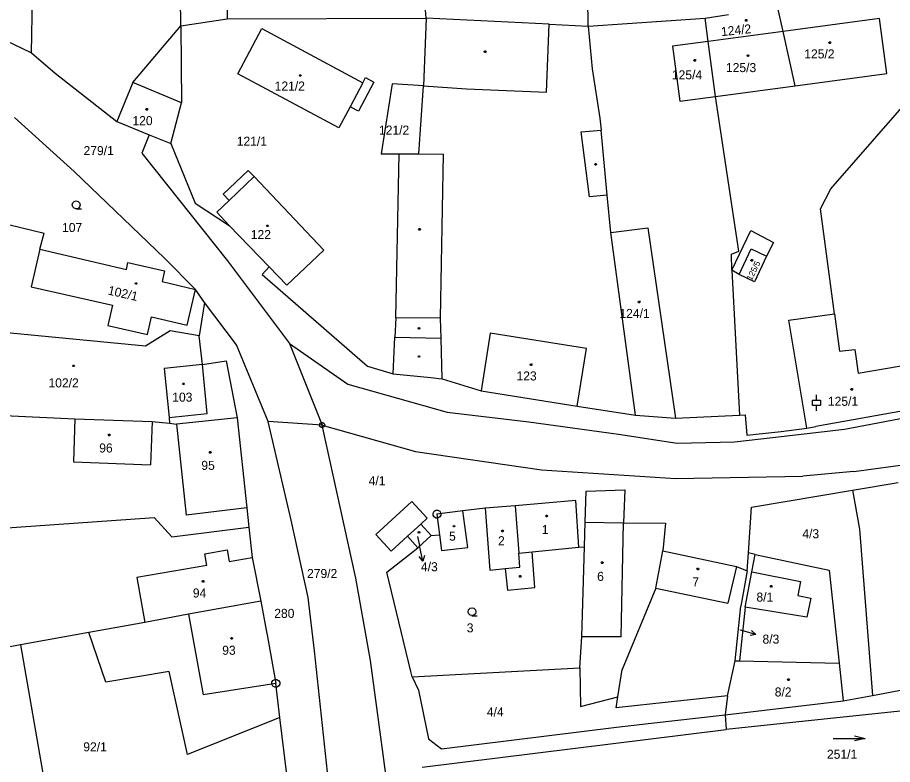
# Model space of a CAD drawing. Extents: x -812394 to -807601, y -1013098 to -1009266.
# Drawn here: x -809776.7 to -809612.2, y -1010813 to -1010672.7 of the extents above; entities that cross this region are included whole.
import ezdxf

# ---------------------------------------------------------------- set-up
doc = ezdxf.new("R2010")
doc.units = 0
for name, color, linetype in [('KN_HRANICE', 7, 'Continuous'), ('KN_KULTURY', 7, 'Continuous'), ('KN_MEZNIKY', 7, 'Continuous'), ('KN_PARCELY', 7, 'Continuous'), ('KN_SLUCKY', 7, 'Continuous')]:
    doc.layers.add(name, color=color, linetype=linetype)

# ---------------------------------------------------------------- blocks, each defined once
blk = doc.blocks.new('101')
blk.add_line((-0.05, 0), (0.05, 0))
blk.add_lwpolyline([(0.19, 0.72), (0.53, 0.53), (0.72, 0.19), (0.72, -0.2), (0.53, -0.54), (0.19, -0.73), (-0.2, -0.73), (-0.54, -0.54), (-0.73, -0.2), (-0.73, 0.19), (-0.54, 0.53), (-0.2, 0.72), (0.19, 0.72)])
blk = doc.blocks.new('304')
blk.add_lwpolyline([(0, 0), (-0.38, 0.1), (-0.65, 0.37), (-0.75, 0.74), (-0.65, 1.11), (-0.38, 1.38), (-0.01, 1.48), (0.36, 1.38), (0.63, 1.11), (0.73, 0.73), (0.63, 0.35), (0.36, 0.08), (-0.02, -0.02), (0.98, -0.02)])
blk = doc.blocks.new('NAHRADNI_SYMBOL')
blk.add_lwpolyline([(0.09, 0.15), (0.18, 0), (0.09, -0.15), (-0.09, -0.15), (-0.18, 0), (-0.09, 0.15), (0.09, 0.15)])
blk = doc.blocks.new('802')
blk.add_line((-3, 0), (3, 0))
blk.add_lwpolyline([(1, 0.5), (3, 0), (1, -0.5)])
blk = doc.blocks.new('10292')
blk.add_line((0, 3), (0, 0))
blk.add_lwpolyline([(-0.5, 2), (0, 3), (0.5, 2)])
blk = doc.blocks.new('318')
blk.add_line((0, 2), (0, 3))
blk.add_lwpolyline([(0, 0), (0, 1), (-0.75, 1), (-0.75, 2), (0, 2), (0.75, 2), (0.75, 1), (0, 1)])
blk = doc.blocks.new('402')
blk.add_lwpolyline([(0.09, 0.15), (0.18, 0), (0.09, -0.15), (-0.09, -0.15), (-0.18, 0), (-0.09, 0.15), (0.09, 0.15)])
blk = doc.blocks.new('105')
blk.add_line((-0.12, 0), (0.12, 0))
blk.add_lwpolyline([(0.15, 0.48), (0.4, 0.3), (0.5, 0.01), (0.4, -0.28), (0.15, -0.46), (-0.16, -0.46), (-0.41, -0.28), (-0.51, 0.01), (-0.41, 0.3), (-0.16, 0.48), (0.15, 0.48)])

msp = doc.modelspace()

# ---------------------------------------------------------------- linework, layer by layer
at = {"layer": 'KN_HRANICE'}
for p, q in [((-809669.42, -1010674.32), (-809670.02, -1010597.72)), ((-809738.29, -1010601.65), (-809737.29, -1010672.93)), ((-809745.99, -1010674.27), (-809746.74, -1010602.54)), ((-809699.85, -1010672.81), (-809703, -1010635.36)), ((-809774.04, -1010679.33), (-809773.49, -1010652.65)), ((-809632.78, -1010675.32), (-809633.83, -1010670.62)), ((-809737.29, -1010672.93), (-809699.85, -1010672.81)), ((-809699.85, -1010672.81), (-809700.37, -1010685.55)), ((-809676.74, -1010673.97), (-809699.85, -1010672.81)), ((-809669.42, -1010674.32), (-809647.44, -1010672.82)), ((-809647.44, -1010672.82), (-809643.04, -1010672.11)), ((-809646.86, -1010677.2), (-809647.44, -1010672.82)), ((-809614.65, -1010672.88), (-809632.78, -1010675.32)), ((-809613.27, -1010683.22), (-809614.65, -1010672.88)), ((-809784.4, -1010674.33), (-809774.04, -1010679.33)), ((-809754.98, -1010684.91), (-809745.99, -1010674.27)), ((-809745.99, -1010674.27), (-809737.29, -1010672.93)), ((-809745.99, -1010674.27), (-809745.83, -1010688.74)), ((-809676.74, -1010673.97), (-809669.42, -1010674.32)), ((-809669.42, -1010674.32), (-809668.69, -1010682.36)), ((-809735.29, -1010683.27), (-809730.75, -1010674.77)), ((-809730.75, -1010674.77), (-809711.79, -1010684.94)), ((-809632.78, -1010675.32), (-809646.86, -1010677.2)), ((-809630.51, -1010685.51), (-809632.78, -1010675.32)), ((-809646.86, -1010677.2), (-809653.59, -1010678.08)), ((-809645.48, -1010687.51), (-809646.86, -1010677.2)), ((-809774.04, -1010679.33), (-809769.56, -1010683.18)), ((-809653.59, -1010678.08), (-809652.21, -1010688.42)), ((-809668.69, -1010682.36), (-809667.2, -1010691.63)), ((-809769.56, -1010683.18), (-809758.03, -1010692.2)), ((-809716.29, -1010693.43), (-809735.29, -1010683.27)), ((-809711.79, -1010684.94), (-809711.27, -1010683.97)), ((-809711.27, -1010683.97), (-809709.68, -1010684.81)), ((-809630.51, -1010685.51), (-809613.27, -1010683.22)), ((-809754.98, -1010684.91), (-809758.03, -1010692.2)), ((-809709.68, -1010684.81), (-809712.59, -1010690.29)), ((-809706.24, -1010685.14), (-809708.32, -1010698.31)), ((-809700.37, -1010685.55), (-809706.24, -1010685.14)), ((-809701.22, -1010698.32), (-809700.37, -1010685.55)), ((-809645.48, -1010687.51), (-809630.51, -1010685.51)), ((-809652.21, -1010688.42), (-809645.48, -1010687.51)), ((-809641.11, -1010716.62), (-809645.48, -1010687.51)), ((-809747.86, -1010696.38), (-809745.83, -1010688.74)), ((-809714.18, -1010689.45), (-809716.29, -1010693.43)), ((-809712.59, -1010690.29), (-809714.18, -1010689.45)), ((-809777.22, -1010691.48), (-809766.01, -1010701.62)), ((-809758.03, -1010692.2), (-809751.95, -1010694.73)), ((-809667.2, -1010691.63), (-809666.99, -1010693.85)), ((-809665.84, -1010706.07), (-809666.99, -1010693.85)), ((-809751.95, -1010694.73), (-809753.31, -1010698.15)), ((-809751.95, -1010694.73), (-809747.86, -1010696.38)), ((-809747.86, -1010696.38), (-809743.3, -1010707.57)), ((-809753.31, -1010698.15), (-809737.22, -1010718.42)), ((-809708.32, -1010698.31), (-809704.94, -1010698.29)), ((-809705.58, -1010729.13), (-809704.94, -1010698.29)), ((-809704.94, -1010698.29), (-809701.22, -1010698.32)), ((-809766.01, -1010701.62), (-809749.02, -1010717.93)), ((-809738.02, -1010705.9), (-809733.32, -1010701.42)), ((-809733.32, -1010701.42), (-809732.21, -1010702.59)), ((-809732.21, -1010702.59), (-809719.07, -1010716.39)), ((-809739.24, -1010709.28), (-809736.91, -1010707.06)), ((-809736.91, -1010707.06), (-809738.02, -1010705.9)), ((-809665.18, -1010713.11), (-809665.84, -1010706.07)), ((-809743.3, -1010707.57), (-809736.88, -1010711.74)), ((-809736.88, -1010711.74), (-809739.24, -1010709.28)), ((-809781.21, -1010710.87), (-809771.66, -1010713.22)), ((-809729.37, -1010719.53), (-809736.88, -1010711.74)), ((-809772.47, -1010716.21), (-809771.66, -1010713.22)), ((-809660.52, -1010747.43), (-809665.18, -1010713.11)), ((-809642.41, -1010720.19), (-809638.87, -1010712.74)), ((-809638.87, -1010712.74), (-809634.6, -1010714.95)), ((-809634.6, -1010714.95), (-809635.89, -1010717.53)), ((-809772.47, -1010716.21), (-809756.21, -1010720.01)), ((-809719.07, -1010716.39), (-809726.06, -1010722.97)), ((-809642.51, -1010717.16), (-809641.11, -1010716.62)), ((-809642.41, -1010720.19), (-809642.51, -1010717.16)), ((-809756.21, -1010720.01), (-809755.91, -1010718.7)), ((-809755.91, -1010718.7), (-809749.04, -1010720.31)), ((-809749.02, -1010717.93), (-809743.23, -1010723.77)), ((-809737.22, -1010718.42), (-809725.56, -1010733.93)), ((-809635.89, -1010717.53), (-809638.17, -1010722.36)), ((-809749.04, -1010720.31), (-809749.51, -1010722.3)), ((-809729.37, -1010719.53), (-809730.7, -1010720.97)), ((-809726.06, -1010722.97), (-809729.37, -1010719.53)), ((-809642.41, -1010720.19), (-809641.01, -1010747.39)), ((-809641.03, -1010721), (-809642.41, -1010720.19)), ((-809730.7, -1010720.97), (-809710.9, -1010738.19)), ((-809638.17, -1010722.36), (-809641.03, -1010721)), ((-809749.51, -1010722.3), (-809743.23, -1010723.77)), ((-809741.5, -1010726.25), (-809743.23, -1010723.77)), ((-809741.5, -1010726.25), (-809742.53, -1010732.53)), ((-809735.54, -1010734.22), (-809741.5, -1010726.25)), ((-809623.13, -1010728.35), (-809622.2, -1010735.4)), ((-809705.58, -1010729.13), (-809705.74, -1010732.73)), ((-809752.63, -1010734.46), (-809779.32, -1010731.85)), ((-809747.95, -1010731.58), (-809752.63, -1010734.46)), ((-809742.53, -1010732.53), (-809747.95, -1010731.58)), ((-809741.93, -1010737.9), (-809742.53, -1010732.53)), ((-809706.04, -1010739.63), (-809705.74, -1010732.73)), ((-809729.55, -1010748.61), (-809735.54, -1010734.22)), ((-809725.56, -1010733.93), (-809719.43, -1010749.27)), ((-809725.56, -1010733.93), (-809714.56, -1010741.6)), ((-809741.93, -1010737.9), (-809749.09, -1010738.63)), ((-809749.09, -1010738.63), (-809748.19, -1010747.84)), ((-809741.93, -1010737.9), (-809737.44, -1010737.2)), ((-809737.44, -1010737.2), (-809735.38, -1010747.89)), ((-809710.9, -1010738.19), (-809706.04, -1010739.63)), ((-809618.66, -1010739.51), (-809608.17, -1010737.7)), ((-809706.04, -1010739.63), (-809698.97, -1010740.34)), ((-809714.56, -1010741.6), (-809695.94, -1010746.84)), ((-809698.97, -1010740.34), (-809697.48, -1010740.51)), ((-809697.48, -1010740.51), (-809696.89, -1010740.57)), ((-809696.89, -1010740.57), (-809689.54, -1010742.83)), ((-809689.54, -1010742.83), (-809671.5, -1010745.72)), ((-809695.94, -1010746.84), (-809680.59, -1010748.64)), ((-809671.5, -1010745.72), (-809660.52, -1010747.43)), ((-809606.66, -1010745.99), (-809626.64, -1010749.55)), ((-809621.25, -1010750.05), (-809601.6, -1010746.29)), ((-809785.91, -1010747.13), (-809765.89, -1010748.07)), ((-809765.89, -1010748.07), (-809766.17, -1010756.16)), ((-809765.89, -1010748.07), (-809751.37, -1010748.58)), ((-809748.19, -1010747.84), (-809748.08, -1010748.94)), ((-809735.38, -1010747.89), (-809746.82, -1010749.08)), ((-809735.38, -1010747.89), (-809733.57, -1010764.79)), ((-809660.52, -1010747.43), (-809652.99, -1010747.99)), ((-809652.99, -1010747.99), (-809641.01, -1010747.39)), ((-809641.01, -1010747.39), (-809639.91, -1010747.34)), ((-809639.91, -1010747.34), (-809639.63, -1010751.19)), ((-809751.37, -1010748.58), (-809751.66, -1010756.76)), ((-809751.37, -1010748.58), (-809748.08, -1010748.94)), ((-809748.08, -1010748.94), (-809746.82, -1010749.08)), ((-809719.43, -1010749.27), (-809729.55, -1010748.61)), ((-809725.23, -1010767.15), (-809729.55, -1010748.61)), ((-809713.08, -1010778.05), (-809719.43, -1010749.27)), ((-809719.43, -1010749.27), (-809701.9, -1010754.25)), ((-809680.59, -1010748.64), (-809663.74, -1010750.97)), ((-809634.81, -1010751.63), (-809621.25, -1010750.05)), ((-809633.16, -1010750.47), (-809628.36, -1010749.86)), ((-809628.36, -1010749.86), (-809626.64, -1010749.55)), ((-809663.74, -1010750.97), (-809652.69, -1010752.68)), ((-809641.93, -1010752.44), (-809634.81, -1010751.63)), ((-809639.63, -1010751.19), (-809633.16, -1010750.47)), ((-809652.69, -1010752.68), (-809641.93, -1010752.44)), ((-809701.9, -1010754.25), (-809678.17, -1010757.69)), ((-809766.17, -1010756.16), (-809751.66, -1010756.76)), ((-809619.48, -1010758), (-809604.22, -1010755.92)), ((-809678.17, -1010757.69), (-809652.96, -1010759.33)), ((-809619.48, -1010758), (-809629.11, -1010758.87)), ((-809652.96, -1010759.33), (-809629.11, -1010758.87)), ((-809669.98, -1010767.52), (-809669.8, -1010761.66)), ((-809669.8, -1010761.66), (-809662.52, -1010761.44)), ((-809662.52, -1010761.44), (-809662.78, -1010767.62)), ((-809638.74, -1010764.69), (-809619.76, -1010761.5)), ((-809619.76, -1010761.5), (-809611.19, -1010760.06)), ((-809619.76, -1010761.5), (-809618.42, -1010768.8)), ((-809733.57, -1010764.79), (-809733.18, -1010768.47)), ((-809702.57, -1010763.63), (-809709.33, -1010769.84)), ((-809699.69, -1010766.77), (-809702.57, -1010763.63)), ((-809688.81, -1010764.89), (-809692.96, -1010765.39)), ((-809683.14, -1010764.42), (-809688.81, -1010764.89)), ((-809688.81, -1010764.89), (-809687.88, -1010776.52)), ((-809671.72, -1010763.46), (-809683.14, -1010764.42)), ((-809683.14, -1010764.42), (-809682.45, -1010773.34)), ((-809671.19, -1010772.24), (-809671.72, -1010763.46)), ((-809639.3, -1010773.28), (-809638.74, -1010764.69)), ((-809692.96, -1010765.39), (-809697.85, -1010765.98)), ((-809697.85, -1010765.98), (-809697.36, -1010769.88)), ((-809692.01, -1010772.28), (-809692.96, -1010765.39)), ((-809794.5, -1010769.7), (-809750.96, -1010766.66)), ((-809750.96, -1010766.66), (-809747.68, -1010770.25)), ((-809722.03, -1010781.65), (-809725.23, -1010767.15)), ((-809700.87, -1010767.86), (-809699.69, -1010766.77)), ((-809698.9, -1010770), (-809700.87, -1010767.86)), ((-809670.12, -1010772.14), (-809669.98, -1010767.52)), ((-809662.78, -1010767.62), (-809654.89, -1010767.73)), ((-809654.89, -1010767.73), (-809655.37, -1010772.93)), ((-809747.68, -1010770.25), (-809733.18, -1010768.47)), ((-809733.18, -1010768.47), (-809732.57, -1010774.14)), ((-809709.33, -1010769.84), (-809706.45, -1010772.98)), ((-809698.9, -1010770), (-809697.36, -1010769.88)), ((-809697.36, -1010769.88), (-809696.98, -1010772.84)), ((-809618.42, -1010768.8), (-809615.96, -1010800.09)), ((-809706.45, -1010772.98), (-809703.38, -1010770.17)), ((-809703.38, -1010770.17), (-809701.41, -1010772.31)), ((-809701.41, -1010772.31), (-809698.9, -1010770)), ((-809707.23, -1010776.9), (-809701.41, -1010772.31)), ((-809696.98, -1010772.84), (-809692.01, -1010772.28)), ((-809682.45, -1010773.34), (-809679.95, -1010773.09)), ((-809679.95, -1010773.09), (-809671.19, -1010772.24)), ((-809679.45, -1010779.76), (-809679.95, -1010773.09)), ((-809671.19, -1010772.24), (-809670.12, -1010772.14)), ((-809670.64, -1010789.08), (-809670.12, -1010772.14)), ((-809656.71, -1010779.93), (-809655.37, -1010772.93)), ((-809655.37, -1010772.93), (-809641.57, -1010775.83)), ((-809732.57, -1010774.14), (-809730.91, -1010782.33)), ((-809639.52, -1010776.68), (-809639.3, -1010773.28)), ((-809638.02, -1010773.59), (-809639.3, -1010773.28)), ((-809638.65, -1010776.84), (-809638.02, -1010773.59)), ((-809638.02, -1010773.59), (-809624.14, -1010776.53)), ((-809687.88, -1010776.52), (-809685.04, -1010776.24)), ((-809685.04, -1010776.24), (-809684.59, -1010780.3)), ((-809641.57, -1010775.83), (-809639.52, -1010776.68)), ((-809710.32, -1010793.53), (-809713.08, -1010778.05)), ((-809702.75, -1010795.56), (-809707.23, -1010776.9)), ((-809639.52, -1010776.68), (-809640.74, -1010783.28)), ((-809639.93, -1010783.49), (-809638.65, -1010776.84)), ((-809624.14, -1010776.53), (-809622.24, -1010794)), ((-809684.59, -1010780.3), (-809679.45, -1010779.76)), ((-809656.71, -1010779.93), (-809663.05, -1010795.21)), ((-809730.91, -1010782.33), (-809744.52, -1010784.82)), ((-809730.91, -1010782.33), (-809729.89, -1010788.11)), ((-809720.85, -1010791.69), (-809722.03, -1010781.65)), ((-809641.81, -1010793.54), (-809640.74, -1010783.28)), ((-809639.93, -1010783.49), (-809640.99, -1010793.56)), ((-809752.77, -1010786.34), (-809763.26, -1010788.24)), ((-809744.52, -1010784.82), (-809752.77, -1010786.34)), ((-809763.26, -1010788.24), (-809776.12, -1010790.59)), ((-809760.07, -1010797.59), (-809763.26, -1010788.24)), ((-809729.89, -1010788.11), (-809729.78, -1010788.7)), ((-809729.78, -1010788.7), (-809728.11, -1010797.8)), ((-809671, -1010794.86), (-809670.64, -1010789.08)), ((-809776.12, -1010790.59), (-809802.82, -1010795.47)), ((-809776.12, -1010790.59), (-809768.91, -1010832.11)), ((-809718.25, -1010816.21), (-809720.85, -1010791.69)), ((-809707.49, -1010814.44), (-809710.32, -1010793.53)), ((-809643.26, -1010800.13), (-809641.81, -1010793.54)), ((-809641.81, -1010793.54), (-809640.99, -1010793.56)), ((-809640.99, -1010793.56), (-809622.24, -1010794)), ((-809622.24, -1010794), (-809621.47, -1010801.11)), ((-809748.14, -1010795.55), (-809760.07, -1010797.59)), ((-809744.75, -1010811.18), (-809748.14, -1010795.55)), ((-809702.5, -1010796.59), (-809702.75, -1010795.56)), ((-809702.5, -1010796.59), (-809671, -1010794.86)), ((-809671, -1010794.86), (-809670.86, -1010802.13)), ((-809663.83, -1010800.36), (-809663.05, -1010795.21)), ((-809615.96, -1010800.09), (-809588.54, -1010794.9)), ((-809727.35, -1010804.19), (-809728.11, -1010797.8)), ((-809702.5, -1010796.59), (-809701.33, -1010799.05)), ((-809701.33, -1010799.05), (-809699.46, -1010808.24)), ((-809670.86, -1010802.13), (-809663.83, -1010800.36)), ((-809664.14, -1010802.41), (-809663.83, -1010800.36)), ((-809643.26, -1010800.13), (-809657.25, -1010801.66)), ((-809643.26, -1010800.13), (-809643.65, -1010803.69)), ((-809643.65, -1010803.69), (-809621.47, -1010801.11)), ((-809621.47, -1010801.11), (-809615.96, -1010800.09)), ((-809657.25, -1010801.66), (-809664.14, -1010802.41)), ((-809600.38, -1010801.89), (-809643.49, -1010806.47)), ((-809727.35, -1010804.19), (-809744.75, -1010811.18)), ((-809726.02, -1010815.44), (-809727.35, -1010804.19)), ((-809657.57, -1010805.27), (-809643.65, -1010803.69)), ((-809643.65, -1010803.69), (-809643.49, -1010806.47)), ((-809696.99, -1010810.11), (-809664.09, -1010806.01)), ((-809664.09, -1010806.01), (-809657.57, -1010805.27)), ((-809700.6, -1010813.52), (-809643.49, -1010806.47)), ((-809699.46, -1010808.24), (-809696.99, -1010810.11))]:
    msp.add_line(p, q, dxfattribs=at)
for points in [[(-809623.13, -1010728.35), (-809625.78, -1010708.61), (-809623.83, -1010704.87), (-809603.55, -1010681.64)], [(-809622.2, -1010735.4), (-809619.34, -1010735.04), (-809618.66, -1010739.51)]]:
    msp.add_lwpolyline(points, dxfattribs=at)
at = {"layer": 'KN_PARCELY'}
for p, q in [((-809701.47, -1010770.18), (-809701.11, -1010771.9)), ((-809640.83, -1010787.76), (-809640.77, -1010787.78))]:
    msp.add_line(p, q, dxfattribs=at)
at = {"layer": 'KN_SLUCKY'}
for p, q in [((-809677.26, -1010686.71), (-809676.74, -1010673.97)), ((-809745.83, -1010688.74), (-809754.98, -1010684.91)), ((-809711.79, -1010684.94), (-809714.18, -1010689.45)), ((-809700.37, -1010685.55), (-809692.3, -1010686.07)), ((-809692.3, -1010686.07), (-809677.26, -1010686.71)), ((-809670.75, -1010694.2), (-809666.99, -1010693.85)), ((-809669.2, -1010706.39), (-809670.75, -1010694.2)), ((-809701.22, -1010698.32), (-809696.59, -1010698.39)), ((-809697.15, -1010729.18), (-809696.59, -1010698.39)), ((-809736.91, -1010707.06), (-809732.21, -1010702.59)), ((-809665.84, -1010706.07), (-809669.2, -1010706.39)), ((-809665.18, -1010713.11), (-809658.18, -1010712.2)), ((-809658.18, -1010712.2), (-809652.99, -1010747.99)), ((-809772.47, -1010716.21), (-809774.12, -1010723.27)), ((-809641.03, -1010721), (-809638.78, -1010716.15)), ((-809638.78, -1010716.15), (-809635.89, -1010717.53)), ((-809774.12, -1010723.27), (-809758.82, -1010726.77)), ((-809744.81, -1010730.49), (-809743.23, -1010723.77)), ((-809758.82, -1010726.77), (-809759.68, -1010730.55)), ((-809631.7, -1010729.58), (-809623.13, -1010728.35)), ((-809752.23, -1010732.25), (-809751.48, -1010728.96)), ((-809751.48, -1010728.96), (-809744.81, -1010730.49)), ((-809697.15, -1010729.18), (-809705.58, -1010729.13)), ((-809697.06, -1010732.94), (-809697.15, -1010729.18)), ((-809628.36, -1010749.86), (-809631.7, -1010729.58)), ((-809759.68, -1010730.55), (-809752.23, -1010732.25)), ((-809687.81, -1010731.99), (-809689.54, -1010742.83)), ((-809669.72, -1010734.88), (-809687.81, -1010731.99)), ((-809705.74, -1010732.73), (-809697.06, -1010732.94)), ((-809696.89, -1010740.57), (-809697.06, -1010732.94)), ((-809671.5, -1010745.72), (-809669.72, -1010734.88)), ((-809741.03, -1010747.11), (-809741.93, -1010737.9)), ((-809748.19, -1010747.84), (-809741.03, -1010747.11)), ((-809746.82, -1010749.08), (-809744.99, -1010766.19)), ((-809733.57, -1010764.79), (-809744.99, -1010766.19)), ((-809703.38, -1010770.17), (-809700.87, -1010767.86)), ((-809669.98, -1010767.52), (-809662.78, -1010767.62)), ((-809663.25, -1010789.07), (-809662.78, -1010767.62)), ((-809741.47, -1010773.44), (-809737.24, -1010772.71)), ((-809737.24, -1010772.71), (-809736.89, -1010774.91)), ((-809741.08, -1010775.63), (-809741.47, -1010773.44)), ((-809736.89, -1010774.91), (-809732.57, -1010774.14)), ((-809682.24, -1010775.95), (-809682.45, -1010773.34)), ((-809741.08, -1010775.63), (-809754.27, -1010777.89)), ((-809685.04, -1010776.24), (-809682.24, -1010775.95)), ((-809641.57, -1010775.83), (-809643.15, -1010782.76)), ((-809754.27, -1010777.89), (-809752.77, -1010786.34)), ((-809638.65, -1010776.84), (-809629.49, -1010778.64)), ((-809629.49, -1010778.64), (-809630.01, -1010781.3)), ((-809656.71, -1010779.93), (-809643.15, -1010782.76)), ((-809630.01, -1010781.3), (-809627.59, -1010781.78)), ((-809627.59, -1010781.78), (-809628.3, -1010785.39)), ((-809628.3, -1010785.39), (-809639.93, -1010783.49)), ((-809744.52, -1010784.82), (-809741.75, -1010799.98)), ((-809663.25, -1010789.07), (-809670.64, -1010789.08)), ((-809728.11, -1010797.8), (-809741.75, -1010799.98))]:
    msp.add_line(p, q, dxfattribs=at)

# ---------------------------------------------------------------- block references
at = {"layer": 'KN_KULTURY'}
for name, p in [('NAHRADNI_SYMBOL', (-809639.73, -1010673.21)), ('402', (-809624.02, -1010677.44)), ('402', (-809688.79, -1010679.1)), ('402', (-809649.39, -1010680.75)), ('402', (-809639.39, -1010679.88)), ('402', (-809723.54, -1010683.59)), ('402', (-809752.37, -1010689.95)), ('402', (-809668.02, -1010700.27)), ('304', (-809765.64, -1010708.64)), ('402', (-809729.71, -1010711.84)), ('402', (-809701.1, -1010712.47)), ('402', (-809638.67, -1010718.34)), ('402', (-809754.39, -1010722.67)), ('402', (-809659.85, -1010726.15)), ('402', (-809701.21, -1010731.09)), ('402', (-809701.21, -1010736.38)), ('NAHRADNI_SYMBOL', (-809766.14, -1010738.14)), ('402', (-809680.15, -1010737.92)), ('402', (-809745.47, -1010741.52)), ('318', (-809626.49, -1010746.61)), ('402', (-809619.88, -1010742.57)), ('402', (-809759.42, -1010751.14)), ('402', (-809740.45, -1010754.37)), ('402', (-809677.22, -1010766.34)), ('402', (-809694.64, -1010768.27)), ('402', (-809701.22, -1010769.4)), ('402', (-809685.53, -1010769.19)), ('402', (-809666.77, -1010775.13)), ('402', (-809648.81, -1010776.33)), ('402', (-809682.2, -1010777.69)), ('402', (-809741.8, -1010778.62)), ('402', (-809635.03, -1010779.55)), ('304', (-809691.24, -1010785.07)), ('402', (-809736.42, -1010789.35)), ('NAHRADNI_SYMBOL', (-809631.79, -1010797.12)), ('802', (-809620.36, -1010808.13))]:
    msp.add_blockref(name, p, dxfattribs=at)
at = {"layer": 'KN_MEZNIKY'}
for name, p in [('105', (-809719.43, -1010749.27)), ('101', (-809697.85, -1010766)), ('101', (-809728.12, -1010797.77))]:
    msp.add_blockref(name, p, dxfattribs=at)
at = {"layer": 'KN_PARCELY'}
for p, rotation in [((-809701.11, -1010771.9), -168.231026), ((-809640.77, -1010787.78), -106.69535899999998)]:
    msp.add_blockref('10292', p, dxfattribs=dict(at, rotation=rotation))

# ---------------------------------------------------------------- texts
for s, height, rotation, p in [('124/2', 1.7, 5.959, (-809644.36, -1010676.21)), ('125/5', 1.14, 63.426, (-809638.7, -1010722.21)), ('102/1', 1.7, 347.27, (-809759.8, -1010724.72))]:
    msp.add_text(s, height=height, rotation=rotation, dxfattribs=at).set_placement(p)
for s, height, p in [('125/2', 1.7, (-809628.81, -1010680.38)), ('125/4', 1.7, (-809653.69, -1010684.31)), ('125/3', 1.7, (-809643.53, -1010682.95)), ('121/2', 1.7, (-809728.34, -1010686.42)), ('120', 1.7, (-809755.07, -1010692.92)), ('121/2', 1.7, (-809708.74, -1010694.7)), ('121/1', 1.7, (-809735.47, -1010696.78)), ('279/1', 1.7, (-809764.26, -1010698.55)), ('107', 1.7, (-809768.3, -1010713)), ('122', 1.7, (-809732.83, -1010714.32)), ('124/1', 1.7, (-809663.55, -1010729.15)), ('123', 1.7, (-809682.89, -1010740.89)), ('102/2', 1.7, (-809770.85, -1010742.19)), ('103', 1.7, (-809747.59, -1010744.87)), ('125/1', 1.7, (-809624.37, -1010745.65)), ('96', 1.7, (-809761.31, -1010754.42)), ('95', 1.7, (-809742.12, -1010757.69)), ('4/1', 1.7, (-809710.68, -1010760.57)), ('1', 1.7, (-809678.15, -1010769.76)), ('5', 1.7, (-809695.57, -1010770.99)), ('4/3', 1.7, (-809629.18, -1010770.54)), ('4/3', 0.1, (-809701.62, -1010770.18)), ('2', 1.7, (-809686.37, -1010771.85)), ('279/2', 1.7, (-809722.26, -1010778.01)), ('4/3', 1.7, (-809700.85, -1010776.74)), ('6', 1.7, (-809667.74, -1010778.55)), ('7', 1.7, (-809649.85, -1010779.58)), ('94', 1.7, (-809743.72, -1010781.67)), ('8/1', 1.7, (-809637.8, -1010782.44)), ('280', 1.7, (-809728.42, -1010785.5)), ('3', 1.7, (-809692.24, -1010788.22)), ('8/3', 0.1, (-809640.98, -1010787.76)), ('8/3', 1.7, (-809636.66, -1010790.34)), ('93', 1.7, (-809738.2, -1010792.43)), ('8/2', 1.7, (-809634.36, -1010800.27)), ('4/4', 1.7, (-809688.46, -1010804.01)), ('92/1', 1.7, (-809764.31, -1010810.58)), ('251/1', 1.7, (-809624.55, -1010811.97))]:
    msp.add_text(s, height=height, dxfattribs=at).set_placement(p)

doc.saveas('drawing.dxf')
